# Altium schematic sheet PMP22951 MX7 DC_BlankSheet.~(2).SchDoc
size 431 x 279 mm; Date: Not shown in title block; ApprovedBy: Not shown in title block; CheckedBy: Not shown in title block; Author: Not shown in title block; CompanyName: Not shown in title block; Engineer: Not shown in title block; Organization: Not shown in title block; Address1: Not shown in title block; Address2: Not shown in title block; Address3: Not shown in title block; Address4: Not shown in title block; DocumentNumber: 2; Revision: Use project parameter SCH_Rev; SheetNumber: 1; SheetTotal: 2; PageSetup: Record=PageOptions¦CenterHorizontal=True¦CenterVertical=True¦PrintScale=1.00¦XCorrection=1.00¦YCorrection=1.00¦PrintKind=0¦BorderSize=5000000¦LeftOffset=0¦BottomOffset=0¦Orientation=2¦PaperLength=1000¦PaperWidth=1000¦Scale=100¦PaperSource=15¦PrintQuality=600¦MediaType=1¦DitherType=10¦PaperKind=Letter¦PrintScaleMode=1
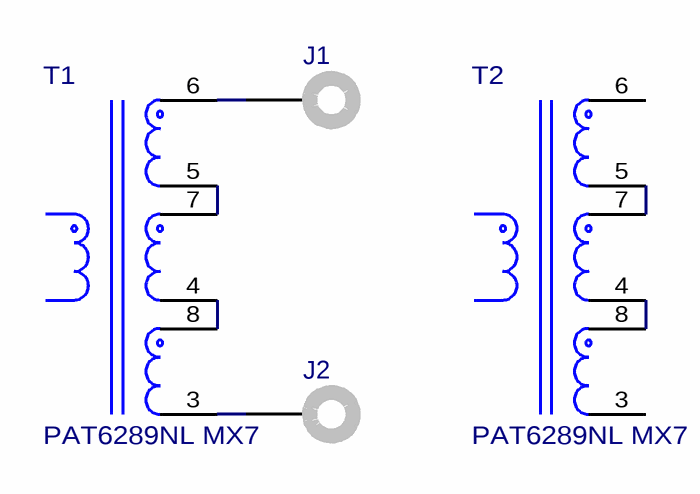
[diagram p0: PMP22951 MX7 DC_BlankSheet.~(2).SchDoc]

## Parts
J1  575-4  [Keystone_575-4]  (value not drawn)
J2  575-4  [Keystone_575-4]  (value not drawn)
T1  PAT6289NL MX7  [FP-PAT6289NL MX7_PTH8_46MM5_27MM0-MFG]
T2  PAT6289NL MX7  [FP-PAT6289NL MX7_PTH8_46MM5_27MM0-MFG]

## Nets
NetJ1_1: J1.1 T1.6
NetJ2_1: J2.1 T1.3
NetT1_4: T1.4 T1.8
NetT1_5: T1.5 T1.7
NetT2_4: T2.4 T2.8
NetT2_5: T2.5 T2.7

Not connected (* = marked no-connect by the designer): T2 3 6

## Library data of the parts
J1 J2 = CMP-0055165-2: Standard Banana Jack, Uninsulated, 5.5mm; Manufacturer: Keystone; CT: TRUE; Green_REACh: Passed; CNHeader: FALSE; Green_Lifecycle: Active
T1 T2 = CMP-0120260-1: Transformer PSFB 2.7kW EW45 TH; Manufacturer: Pulse; DCR_ohm: 37m; Ind_H: 565µH; Ns1toNp: 16:1; Rsec1_ohm: 380µ; SizeZ_mm: 32.5mm; AEC Qualified: No; Frequency_Fixed: 140-200kHz; Voltage_Isolation_Vrms: 3kV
